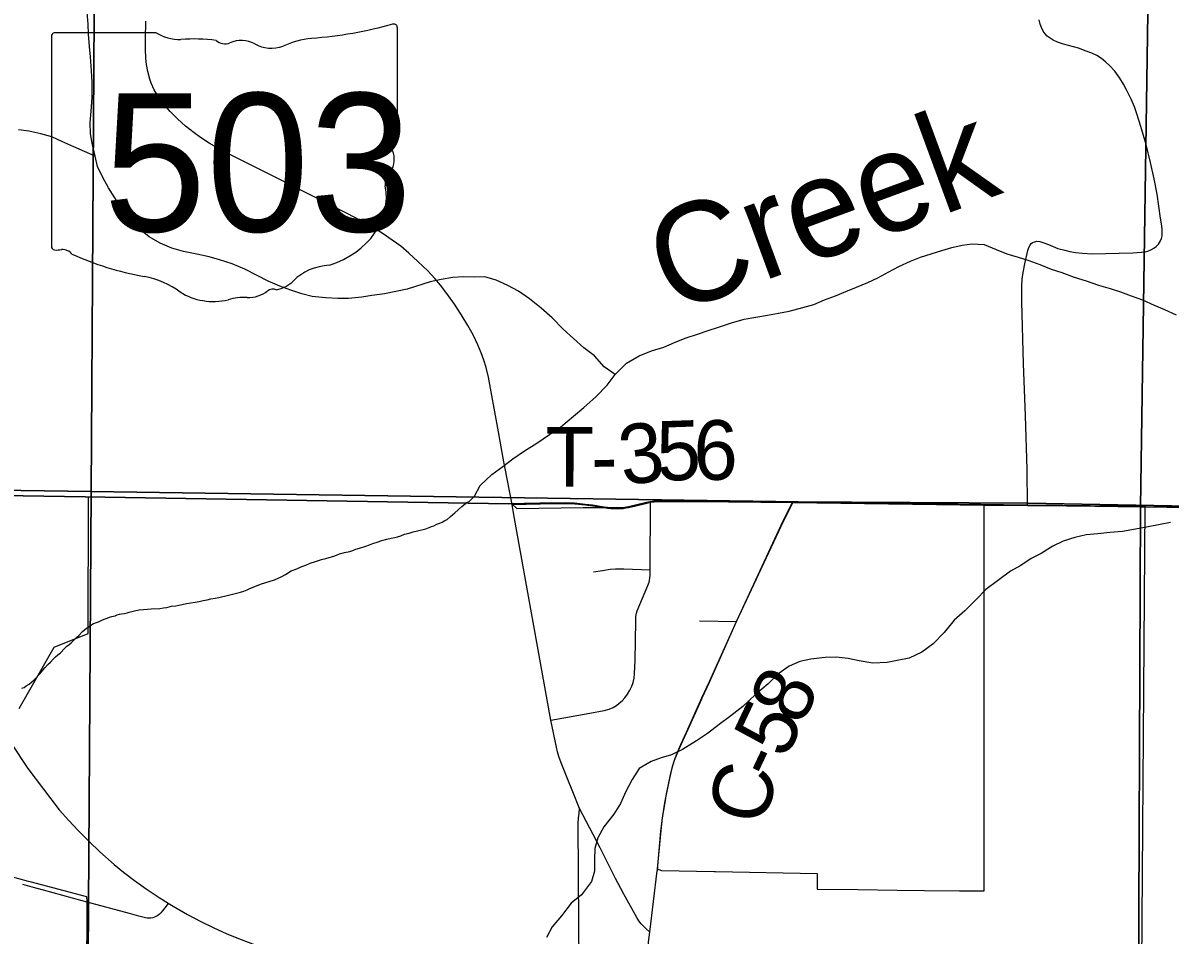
# Model space of a CAD drawing. Extents: x 0 to 34, y 0 to 22.
# Drawn here: x 6.414 to 7.507, y 17.907 to 18.776 of the extents above; entities that cross this region are included whole.
import ezdxf

# ---------------------------------------------------------------- set-up
doc = ezdxf.new("R2010")
doc.units = 0
for name, color, linetype in [('GM_X_City_Street', 7, 'Continuous'), ('GM_X_Corporation', 7, 'Continuous'), ('GM_X_County_Road', 7, 'Continuous'), ('GM_X_County_Road_Text', 7, 'Continuous'), ('GM_X_Minor_River', 7, 'Continuous'), ('GM_X_Minor_River_Text', 7, 'Continuous'), ('GM_X_State_Location', 7, 'Continuous'), ('GM_X_State_Route', 7, 'Continuous'), ('GM_X_State_Shield', 7, 'Continuous'), ('GM_X_Township_Road', 7, 'Continuous'), ('GM_X_Township_Road_Text', 7, 'Continuous')]:
    doc.layers.add(name, color=color, linetype=linetype)

msp = doc.modelspace()

# ---------------------------------------------------------------- linework, layer by layer
at = {"layer": 'GM_X_City_Street'}
msp.add_line((7.0586, 18.2066), (7.0939, 18.2059), dxfattribs=at)
for points in [[(6.9168, 18.1118), (6.9542, 18.1186), (6.9677, 18.1211), (6.9724, 18.1224), (6.9764, 18.1241), (6.9795, 18.126), (6.9821, 18.128), (6.9849, 18.1305), (6.9874, 18.1332), (6.99, 18.1367), (6.9922, 18.1404), (6.994, 18.1443), (6.9954, 18.1479), (6.9963, 18.1521), (6.9968, 18.1565), (6.9973, 18.1688), (6.9978, 18.2064), (6.998, 18.2107), (6.9985, 18.214), (6.9992, 18.216), (7.0095, 18.2404), (7.0107, 18.2433), (7.0113, 18.2469), (7.0116, 18.2505), (7.0116, 18.2552), (7.012, 18.3196)], [(6.9576, 18.2533), (6.9661, 18.2547), (6.9735, 18.2557), (6.9785, 18.256), (6.9866, 18.2561), (7.0116, 18.2552)], [(7.0111, 17.9099), (7.0073, 17.9134), (7.0051, 17.9155), (7.003, 17.9178), (7.0007, 17.9207), (6.9988, 17.9238), (6.9864, 17.9461), (6.9836, 17.9516), (6.9786, 17.9609), (6.9639, 17.9903), (6.9442, 18.0278)]]:
    msp.add_lwpolyline(points, dxfattribs=at)
at = {"layer": 'GM_X_Corporation'}
for points in [[(6.4855, 19.3379), (6.4791, 18.3297), (5.4991, 18.3437), (5.4612, 18.3442), (5.4859, 19.36)], [(7.4935, 19.3206), (7.4788, 18.3152), (6.4791, 18.3297), (6.4855, 19.3379)], [(8.496, 19.3116), (8.4911, 18.3026), (7.4788, 18.3152), (7.4935, 19.3206)], [(5.4991, 18.3437), (6.4791, 18.3297), (6.4721, 17.2442), (5.4781, 17.2612)], [(6.4791, 18.3297), (7.4788, 18.3152), (7.4742, 17.2327), (6.4721, 17.2442)], [(8.4911, 18.3026), (8.489, 17.2189), (7.4742, 17.2327), (7.4788, 18.3152)]]:
    msp.add_lwpolyline(points, close=True, dxfattribs=at)
for points in [[(7.5425, 18.3154), (7.3717, 18.3187), (7.1473, 18.32), (7.0554, 18.3207), (7.0374, 18.321), (7.025, 18.3212), (7.0182, 18.3209), (7.0152, 18.3206), (7.0082, 18.3194), (6.9908, 18.3151), (6.9855, 18.3144), (6.9799, 18.3141), (6.9772, 18.314), (6.9676, 18.315), (6.9567, 18.3168), (6.9498, 18.3176), (6.9395, 18.3186), (6.9306, 18.319), (6.9066, 18.3187), (6.8766, 18.3181), (6.4733, 18.3247), (6.2367, 18.3286)], [(6.2367, 18.3286), (6.4733, 18.3247), (6.8766, 18.3181), (6.9066, 18.3187), (6.9306, 18.319), (6.9395, 18.3186), (6.9498, 18.3176), (6.9567, 18.3168), (6.9676, 18.315), (6.9772, 18.314), (6.9799, 18.3141), (6.9855, 18.3144), (6.9908, 18.3151), (7.0082, 18.3194), (7.0152, 18.3206), (7.0182, 18.3209), (7.025, 18.3212), (7.0374, 18.321), (7.0554, 18.3207), (7.1473, 18.32), (7.3717, 18.3187), (7.5425, 18.3154)], [(6.4105, 18.1229), (6.4437, 18.1814), (6.476, 18.1946), (6.4766, 18.322), (6.4766, 18.3249), (6.8798, 18.318), (6.8846, 18.3135), (6.9478, 18.3145), (6.9705, 18.3147), (6.9884, 18.3148), (7.0043, 18.3183), (7.0082, 18.3194), (7.0118, 18.3202), (7.1473, 18.32), (7.1362, 18.2974), (7.0937, 18.2064), (7.0677, 18.1486), (7.0605, 18.1329), (7.046, 18.1003), (7.0406, 18.0885), (7.0376, 18.0818), (7.0346, 18.0743), (7.0327, 18.0684), (7.0306, 18.0599), (7.0287, 18.0507), (7.0268, 18.0416), (7.0254, 18.0336), (7.0231, 18.019), (7.0216, 18.0067), (7.0182, 17.9701), (7.0224, 17.9686), (7.0725, 17.9676), (7.0739, 17.9676), (7.1708, 17.9657), (7.1707, 17.9508), (7.1711, 17.9508), (7.2097, 17.9504), (7.2469, 17.9499), (7.2729, 17.9496), (7.3064, 17.9492), (7.3299, 17.9492), (7.3299, 18.3174), (7.3304, 18.3174), (7.3708, 18.317), (7.4048, 18.3167), (7.4829, 18.3159), (7.4779, 17.6151)], [(6.4739, 17.6399), (6.4752, 17.9391), (6.475, 17.9436), (6.421, 17.9579), (6.4193, 17.9583), (6.401, 17.9631)]]:
    msp.add_lwpolyline(points, dxfattribs=at)
at = {"layer": 'GM_X_County_Road'}
for p, q in [((7.1475, 18.3195), (7.3297, 18.3169)), ((7.0111, 17.9099), (7.0183, 17.9682)), ((7.0183, 17.9682), (7.0184, 17.9692))]:
    msp.add_line(p, q, dxfattribs=at)
for points in [[(7.0837, 18.1831), (7.0939, 18.2059), (7.1364, 18.2969), (7.1475, 18.3195)], [(7.3297, 18.3169), (7.3307, 18.3169), (7.3711, 18.3165), (7.4829, 18.3154)], [(7.4829, 18.3154), (7.5815, 18.3145), (7.7256, 18.3124), (7.7635, 18.3119)], [(7.0611, 18.1333), (7.068, 18.148), (7.0837, 18.1831)], [(7.0184, 17.9692), (7.0218, 18.0062), (7.0234, 18.0184), (7.0257, 18.0331), (7.0271, 18.041), (7.0289, 18.0502), (7.0309, 18.0593), (7.033, 18.0678), (7.0349, 18.0738), (7.0378, 18.0813), (7.0408, 18.088), (7.0462, 18.0998), (7.0607, 18.1324), (7.0611, 18.1333)], [(7.01, 17.8396), (7.01, 17.8435), (7.0101, 17.9003), (7.0105, 17.9052), (7.0111, 17.9099)]]:
    msp.add_lwpolyline(points, dxfattribs=at)
at = {"layer": 'GM_X_Minor_River'}
for points in [[(6.9783, 18.4413), (6.9678, 18.4487), (6.9585, 18.4592), (6.9484, 18.4669), (6.9384, 18.4758), (6.9287, 18.4847), (6.9182, 18.4952), (6.9078, 18.5045), (6.8965, 18.5134), (6.8861, 18.5208), (6.8759, 18.5263), (6.865, 18.5314), (6.8541, 18.5343), (6.8438, 18.5341), (6.8339, 18.5343), (6.8237, 18.5337), (6.8123, 18.532), (6.802, 18.5296), (6.7802, 18.5228), (6.7692, 18.5203), (6.7585, 18.5182), (6.7464, 18.5166), (6.7368, 18.5152), (6.7243, 18.5139), (6.7141, 18.5138), (6.7023, 18.5144), (6.6894, 18.5157), (6.6796, 18.5182), (6.6691, 18.5218), (6.6589, 18.5254), (6.6476, 18.5302), (6.6371, 18.5357), (6.6254, 18.5416), (6.6134, 18.5467), (6.6013, 18.5507), (6.5915, 18.5536), (6.5798, 18.5561), (6.5669, 18.5586), (6.556, 18.5618), (6.5447, 18.5666), (6.5342, 18.5725), (6.5229, 18.5818), (6.5133, 18.5926), (6.5055, 18.6037), (6.4956, 18.6194), (6.49, 18.629), (6.4849, 18.6397), (6.4828, 18.6493), (6.4804, 18.6603), (6.4783, 18.6706), (6.4781, 18.6816), (6.4791, 18.6922), (6.4801, 18.7054), (6.4799, 18.7199), (6.4794, 18.7309), (6.4785, 18.7442), (6.4775, 18.754), (6.4766, 18.7658), (6.476, 18.7753), (6.4751, 18.7867)], [(6.4828, 18.6493), (6.4727, 18.654), (6.4625, 18.6584), (6.4512, 18.6635), (6.4414, 18.6679), (6.4312, 18.6707), (6.4195, 18.6732), (6.4097, 18.6745)], [(6.8443, 18.3255), (6.8496, 18.3357), (6.8608, 18.3461), (6.8712, 18.3538), (6.8808, 18.3609), (6.892, 18.3686), (6.9035, 18.376), (6.9158, 18.3841), (6.9266, 18.3915), (6.9385, 18.4015), (6.9485, 18.41), (6.9597, 18.4201), (6.9705, 18.4313), (6.9783, 18.4413), (6.9891, 18.4521), (7.001, 18.4591), (7.0129, 18.4638), (7.0247, 18.4674), (7.0347, 18.4718), (7.045, 18.4761), (7.0568, 18.4797), (7.0667, 18.4833), (7.0767, 18.4865), (7.0889, 18.4905), (7.1011, 18.4941), (7.1121, 18.4961), (7.1235, 18.4978), (7.1338, 18.4999), (7.1441, 18.5016), (7.1571, 18.5052), (7.1674, 18.508), (7.1777, 18.5124), (7.188, 18.5163), (7.1979, 18.5203), (7.2083, 18.5247), (7.219, 18.529), (7.2285, 18.5334), (7.2389, 18.5393), (7.2485, 18.5444), (7.2596, 18.5495), (7.2691, 18.5531), (7.2794, 18.5564), (7.2893, 18.5596), (7.2989, 18.5624), (7.3088, 18.5645), (7.3183, 18.5659), (7.3297, 18.5653), (7.3413, 18.5605), (7.3515, 18.5565), (7.3621, 18.5533), (7.3723, 18.5501), (7.3828, 18.5461), (7.3937, 18.5417), (7.4039, 18.5385), (7.4156, 18.5341), (7.4269, 18.5305), (7.4386, 18.5265), (7.4499, 18.5232), (7.4597, 18.52), (7.4699, 18.5164), (7.4805, 18.5124), (7.4917, 18.5073), (7.5015, 18.5033), (7.5128, 18.4982)], [(6.519, 18.2158), (6.5217, 18.2165), (6.5247, 18.2171), (6.5289, 18.2174), (6.5327, 18.2176), (6.5361, 18.2179), (6.5445, 18.2183), (6.5479, 18.219), (6.551, 18.2192), (6.5556, 18.2206), (6.5597, 18.2208), (6.5624, 18.2215), (6.5658, 18.2221), (6.5697, 18.2231), (6.5739, 18.2237), (6.578, 18.2243), (6.5819, 18.225), (6.5857, 18.226), (6.5895, 18.2266), (6.5929, 18.2276), (6.5971, 18.2282), (6.6006, 18.2288), (6.6032, 18.2295), (6.6074, 18.2305), (6.6124, 18.2318), (6.6174, 18.2328), (6.6212, 18.2338), (6.6243, 18.2348), (6.6277, 18.2362), (6.6308, 18.2377), (6.6335, 18.2387), (6.6404, 18.2415), (6.6538, 18.2456), (6.66, 18.2484), (6.6643, 18.2509), (6.6697, 18.2541), (6.6751, 18.2562), (6.6797, 18.2583), (6.6835, 18.2597), (6.6878, 18.2615), (6.6927, 18.2632), (6.6985, 18.2649), (6.7027, 18.2659), (6.7111, 18.2686), (6.7157, 18.2704), (6.7203, 18.2717), (6.7253, 18.2727), (6.7284, 18.2737), (6.731, 18.2748), (6.7345, 18.2758), (6.7406, 18.2778), (6.7441, 18.2789), (6.7475, 18.2802), (6.7514, 18.2816), (6.756, 18.283), (6.7606, 18.2843), (6.7648, 18.2853), (6.7682, 18.286), (6.7709, 18.2866), (6.7739, 18.2877), (6.7774, 18.2891), (6.782, 18.29), (6.7858, 18.2914), (6.79, 18.2924), (6.7977, 18.2944), (6.8011, 18.2954), (6.8034, 18.2965), (6.8054, 18.2972), (6.8084, 18.2986), (6.8111, 18.2996), (6.8134, 18.3007), (6.8158, 18.3021), (6.8181, 18.3032), (6.8212, 18.3061), (6.8236, 18.308), (6.8255, 18.3094), (6.8322, 18.3156), (6.8341, 18.3171), (6.8368, 18.3193), (6.8392, 18.3203), (6.8423, 18.3236), (6.8443, 18.3255)], [(7.5073, 18.3004), (7.4974, 18.2983), (7.486, 18.2962), (7.4738, 18.2938), (7.4616, 18.2917), (7.4494, 18.2908), (7.438, 18.2895), (7.427, 18.2886), (7.416, 18.2861), (7.4049, 18.2825), (7.3953, 18.2778), (7.3842, 18.2708), (7.3746, 18.266), (7.3646, 18.2594), (7.3547, 18.2539), (7.3424, 18.2446), (7.3312, 18.2365), (7.3223, 18.2268), (7.3115, 18.216), (7.3011, 18.2071), (7.2917, 18.1955), (7.2813, 18.1847), (7.2705, 18.1766), (7.2583, 18.1711), (7.2469, 18.1687), (7.2373, 18.1669), (7.2237, 18.1664), (7.2108, 18.1686), (7.2002, 18.1707), (7.1889, 18.172), (7.1782, 18.1718), (7.1646, 18.1702), (7.1543, 18.1677), (7.1439, 18.1634), (7.1343, 18.1563), (7.1239, 18.1467), (7.1119, 18.1363), (7.1, 18.1251), (7.0884, 18.1159), (7.0773, 18.1077), (7.0661, 18.0992), (7.0557, 18.0922), (7.0423, 18.0841), (7.032, 18.079), (7.0221, 18.0761), (7.0125, 18.0725), (7.001, 18.0659), (6.9944, 18.0554), (6.9885, 18.0438), (6.9833, 18.0325), (6.9771, 18.0224), (6.9674, 18.0104), (6.9618, 17.9999), (6.959, 17.9897), (6.9584, 17.9791), (6.9586, 17.9681), (6.9558, 17.9583), (6.946, 17.9456), (6.9364, 17.9374), (6.9271, 17.9255), (6.9182, 17.915), (6.9127, 17.9049)], [(6.4129, 18.1424), (6.4152, 18.1431), (6.4172, 18.1445), (6.4199, 18.1463), (6.4222, 18.1481), (6.4246, 18.1503), (6.4301, 18.1562), (6.4329, 18.1595), (6.4352, 18.1621), (6.4376, 18.1651), (6.4404, 18.1673), (6.4427, 18.1702), (6.4451, 18.1724), (6.4474, 18.1742), (6.4498, 18.1761), (6.4537, 18.1801), (6.4557, 18.1823), (6.458, 18.1841), (6.4599, 18.1856), (6.4631, 18.1889), (6.4654, 18.1911), (6.4674, 18.1926), (6.4706, 18.1963), (6.4725, 18.1981), (6.4745, 18.1995), (6.4768, 18.201), (6.4787, 18.2024), (6.4811, 18.2039), (6.4841, 18.2049), (6.486, 18.2056), (6.488, 18.2067), (6.4899, 18.2074), (6.4922, 18.2084), (6.4941, 18.2091), (6.4964, 18.2102), (6.4987, 18.2108), (6.5018, 18.2115), (6.5037, 18.2122), (6.506, 18.2129), (6.5079, 18.2132), (6.5106, 18.2135), (6.5133, 18.2141), (6.5152, 18.2148), (6.519, 18.2158)]]:
    msp.add_lwpolyline(points, dxfattribs=at)
at = {"layer": 'GM_X_State_Route'}
msp.add_line((6.8818, 18.3077), (6.88, 18.3175), dxfattribs=at)
for points in [[(6.8723, 18.358), (6.8671, 18.3868), (6.8602, 18.4247), (6.8574, 18.4387), (6.8552, 18.4479), (6.8531, 18.4551), (6.8506, 18.4621), (6.8474, 18.4696), (6.8428, 18.4791), (6.838, 18.4879), (6.8316, 18.4986), (6.8251, 18.5085), (6.8179, 18.5187), (6.8117, 18.5265), (6.8065, 18.5327), (6.7996, 18.54), (6.7903, 18.5491), (6.7816, 18.5571), (6.7739, 18.5635), (6.7659, 18.5695), (6.7571, 18.5754), (6.7465, 18.582), (6.7357, 18.5881), (6.723, 18.5948), (6.662, 18.6256), (6.6359, 18.6387), (6.6187, 18.6473), (6.6033, 18.6552), (6.5915, 18.6619), (6.5832, 18.6673), (6.5772, 18.6716), (6.5689, 18.6781), (6.5611, 18.6851), (6.5542, 18.692), (6.5497, 18.6971), (6.5451, 18.7029), (6.5427, 18.7064), (6.539, 18.7128), (6.5363, 18.7189), (6.5348, 18.7229), (6.5329, 18.73), (6.5318, 18.7367), (6.5312, 18.7428), (6.5308, 18.7515), (6.5308, 18.7608), (6.5311, 18.7781)], [(6.88, 18.3175), (6.8731, 18.3532), (6.8723, 18.358)], [(6.9438, 17.7814), (6.9441, 17.8441), (6.9435, 17.9171), (6.9431, 18.0135), (6.9434, 18.0189), (6.9438, 18.023), (6.9442, 18.0278), (6.9268, 18.0713), (6.9246, 18.0774), (6.9233, 18.0819), (6.9223, 18.0861), (6.9168, 18.1118), (6.8818, 18.3077)], [(6.3872, 18.1128), (6.4186, 18.0659), (6.4486, 18.0265), (6.4576, 18.0162), (6.4665, 18.0067), (6.477, 17.9962), (6.4874, 17.9864), (6.5009, 17.9745), (6.5099, 17.967), (6.5203, 17.9591), (6.5314, 17.9512), (6.5438, 17.943), (6.5525, 17.9376), (6.557, 17.9348), (6.5709, 17.9268), (6.5841, 17.9197), (6.5952, 17.9143), (6.6082, 17.9084), (6.622, 17.9028), (6.6353, 17.8978), (6.6459, 17.8942), (6.6631, 17.889), (6.6785, 17.8848)]]:
    msp.add_lwpolyline(points, dxfattribs=at)
at = {"layer": 'GM_X_State_Shield'}
for p, q in [((6.5409, 18.7671), (6.4443, 18.7671)), ((6.7707, 18.6673), (6.7707, 18.772)), ((6.4411, 18.7636), (6.4411, 18.5635)), ((6.7706, 18.6674), (6.7707, 18.6673))]:
    msp.add_line(p, q, dxfattribs=at)
for centre, major_axis, start_param, end_param in [((6.6533, 19.0399), (0.3495, 0), 4.814394, 5.042369), ((6.767, 18.7724), (0.00367, 0), 6.141152, 7.989035), ((6.4449, 18.764), (0.00382, 0), 1.712693, 3.28349), ((6.5638, 18.7903), (0.037, 0), 4.042523, 4.731795), ((6.5761, 18.6547), (0.133, 0), 1.404758, 1.657858), ((6.6063, 18.7651), (0.0107, 0), 3.836095, 5.185415), ((6.622, 18.7419), (0.0222, 0), 0.950623, 2.079405), ((6.6507, 18.7737), (0.0267, 0), 4.081561, 5.145723), ((6.6979, 18.7059), (0.0703, 0), 1.699011, 2.107814), ((6.7668, 18.6669), (0.00393, 0), 5.05454, 6.418171), ((6.7698, 18.6596), (0.00568, 0), 1.883978, 3.671073), ((6.7337, 18.6464), (0.0341, 0), 5.934695, 6.695948), ((6.7838, 18.6235), (0.0248, 0), 2.387724, 3.262537), ((6.6729, 18.6102), (0.0874, 0), 5.101752, 6.440018), ((6.4449, 18.5631), (0.00385, 0), 3.00124, 4.508301), ((6.4455, 18.5835), (0.0294, 0), 4.665946, 4.897461), ((6.4515, 18.5519), (0.0106, 0), 0.519207, 1.627899), ((6.5853, 18.7317), (0.2524, 0), 4.195997, 4.488961), ((6.7097, 18.5073), (0.0479, 0), 1.647645, 2.488434), ((6.5101, 18.4736), (0.079, 0), 0.823519, 1.323587), ((6.6491, 18.5441), (0.0282, 0), 4.937069, 5.64225), ((6.5955, 18.551), (0.0501, 0), 4.026481, 4.996735), ((6.6244, 18.4818), (0.0412, 0), 1.495662, 1.94098), ((6.6281, 18.536), (0.0267, 0), 4.691044, 5.507374), ((6.6523, 18.5166), (0.00752, 0), 1.147584, 2.315152)]:
    msp.add_ellipse(centre, major_axis=major_axis, ratio=0.8, start_param=start_param, end_param=end_param, dxfattribs=at)
at = {"layer": 'GM_X_Township_Road'}
for points in [[(7.3711, 18.3165), (7.3707, 18.3509), (7.3691, 18.4024), (7.3674, 18.4515), (7.3656, 18.5105), (7.3657, 18.5254), (7.3661, 18.5322), (7.3669, 18.5384), (7.3686, 18.5469), (7.3714, 18.5594), (7.3723, 18.5624), (7.3735, 18.5647), (7.3747, 18.5662), (7.3759, 18.567), (7.3779, 18.5679), (7.38, 18.5683), (7.3827, 18.568), (7.3867, 18.5667), (7.3912, 18.5651), (7.4001, 18.5615), (7.4065, 18.5597), (7.4115, 18.5585), (7.4169, 18.5575), (7.4235, 18.5569), (7.4328, 18.5565), (7.4715, 18.5573), (7.4796, 18.5578), (7.4833, 18.5582), (7.4858, 18.5589), (7.4887, 18.5602), (7.4913, 18.5616), (7.4935, 18.5632), (7.4958, 18.5657), (7.4977, 18.5686), (7.4986, 18.5711), (7.4992, 18.5736), (7.4994, 18.5768), (7.4993, 18.5802), (7.4987, 18.5848), (7.4979, 18.5904), (7.4945, 18.6131), (7.4917, 18.6278), (7.4882, 18.6435), (7.484, 18.6604), (7.4791, 18.6777), (7.4752, 18.6899), (7.473, 18.6963), (7.4698, 18.7037), (7.4655, 18.7126), (7.4625, 18.7181), (7.4589, 18.7239), (7.4542, 18.7304), (7.4495, 18.7355), (7.4457, 18.739), (7.4414, 18.7426), (7.437, 18.7454), (7.4325, 18.7475), (7.4271, 18.7496), (7.4196, 18.7522), (7.4052, 18.7561), (7.3996, 18.7581), (7.3956, 18.76), (7.3926, 18.7618), (7.3899, 18.7638), (7.388, 18.7659), (7.386, 18.7685), (7.3843, 18.7719), (7.3831, 18.7753), (7.3822, 18.7794)], [(6.88, 18.3175), (6.9068, 18.3182), (6.9199, 18.3185), (6.9309, 18.3184), (6.9397, 18.3181), (6.9501, 18.3171), (6.9569, 18.3162), (6.9679, 18.3145), (6.971, 18.3141), (6.974, 18.3138), (6.9775, 18.3135), (6.9801, 18.3135), (6.9858, 18.3138), (6.9884, 18.3142), (6.991, 18.3146), (6.9966, 18.3158), (7.0084, 18.3188), (7.012, 18.3196), (7.0154, 18.3201), (7.0184, 18.3203), (7.0253, 18.3206), (7.0377, 18.3205), (7.0557, 18.3202), (7.1475, 18.3195)], [(6.4752, 17.9386), (6.4703, 17.9399), (6.4337, 17.9498), (6.4229, 17.9527), (6.4139, 17.9552)], [(6.5525, 17.9376), (6.5513, 17.9358), (6.5471, 17.9301), (6.5455, 17.9282), (6.5441, 17.927), (6.5425, 17.9259), (6.5407, 17.9249), (6.5393, 17.9242), (6.5377, 17.9236), (6.536, 17.9232), (6.5348, 17.9232), (6.5336, 17.9232), (6.5324, 17.9233), (6.5308, 17.9236), (6.5245, 17.9252), (6.5156, 17.9276), (6.4752, 17.9386)]]:
    msp.add_lwpolyline(points, dxfattribs=at)

# ---------------------------------------------------------------- texts
at = {"layer": 'GM_X_County_Road_Text'}
for s, rotation, p in [('8', 64.7952, (7.1555, 18.1053)), ('5', 64.7699, (7.1406, 18.0736)), ('-', 64.6516, (7.1306, 18.0524)), ('C', 77.1533, (7.1212, 18.01))]:
    msp.add_text(s, height=0.0568, rotation=rotation, dxfattribs=at).set_placement(p)
at = {"layer": 'GM_X_Minor_River_Text'}
msp.add_text('Creek', height=0.09469, rotation=20.1996, dxfattribs=at).set_placement((7.0321, 18.4981))
at = {"layer": 'GM_X_State_Location'}
for s in ['s', 'r']:
    msp.add_text(s, height=0.000189, dxfattribs=at).set_placement((6.6022, 18.6502))
msp.add_text('503', height=0.000189, rotation=0, dxfattribs=at).set_placement((6.5353, 18.6365))
at = {"layer": 'GM_X_State_Shield'}
msp.add_text('503', height=0.13184, dxfattribs=at).set_placement((6.4906, 18.5776))
at = {"layer": 'GM_X_Township_Road_Text'}
for s, rotation, p in [('3', 7.486, (6.9856, 18.3355)), ('5', 1.9534, (7.0185, 18.3399)), ('6', 359.7686, (7.0527, 18.3411)), ('T', 359.8988, (6.9118, 18.3346)), ('-', 1.2214, (6.9557, 18.3345))]:
    msp.add_text(s, height=0.0568, rotation=rotation, dxfattribs=at).set_placement(p)

doc.saveas('drawing.dxf')
